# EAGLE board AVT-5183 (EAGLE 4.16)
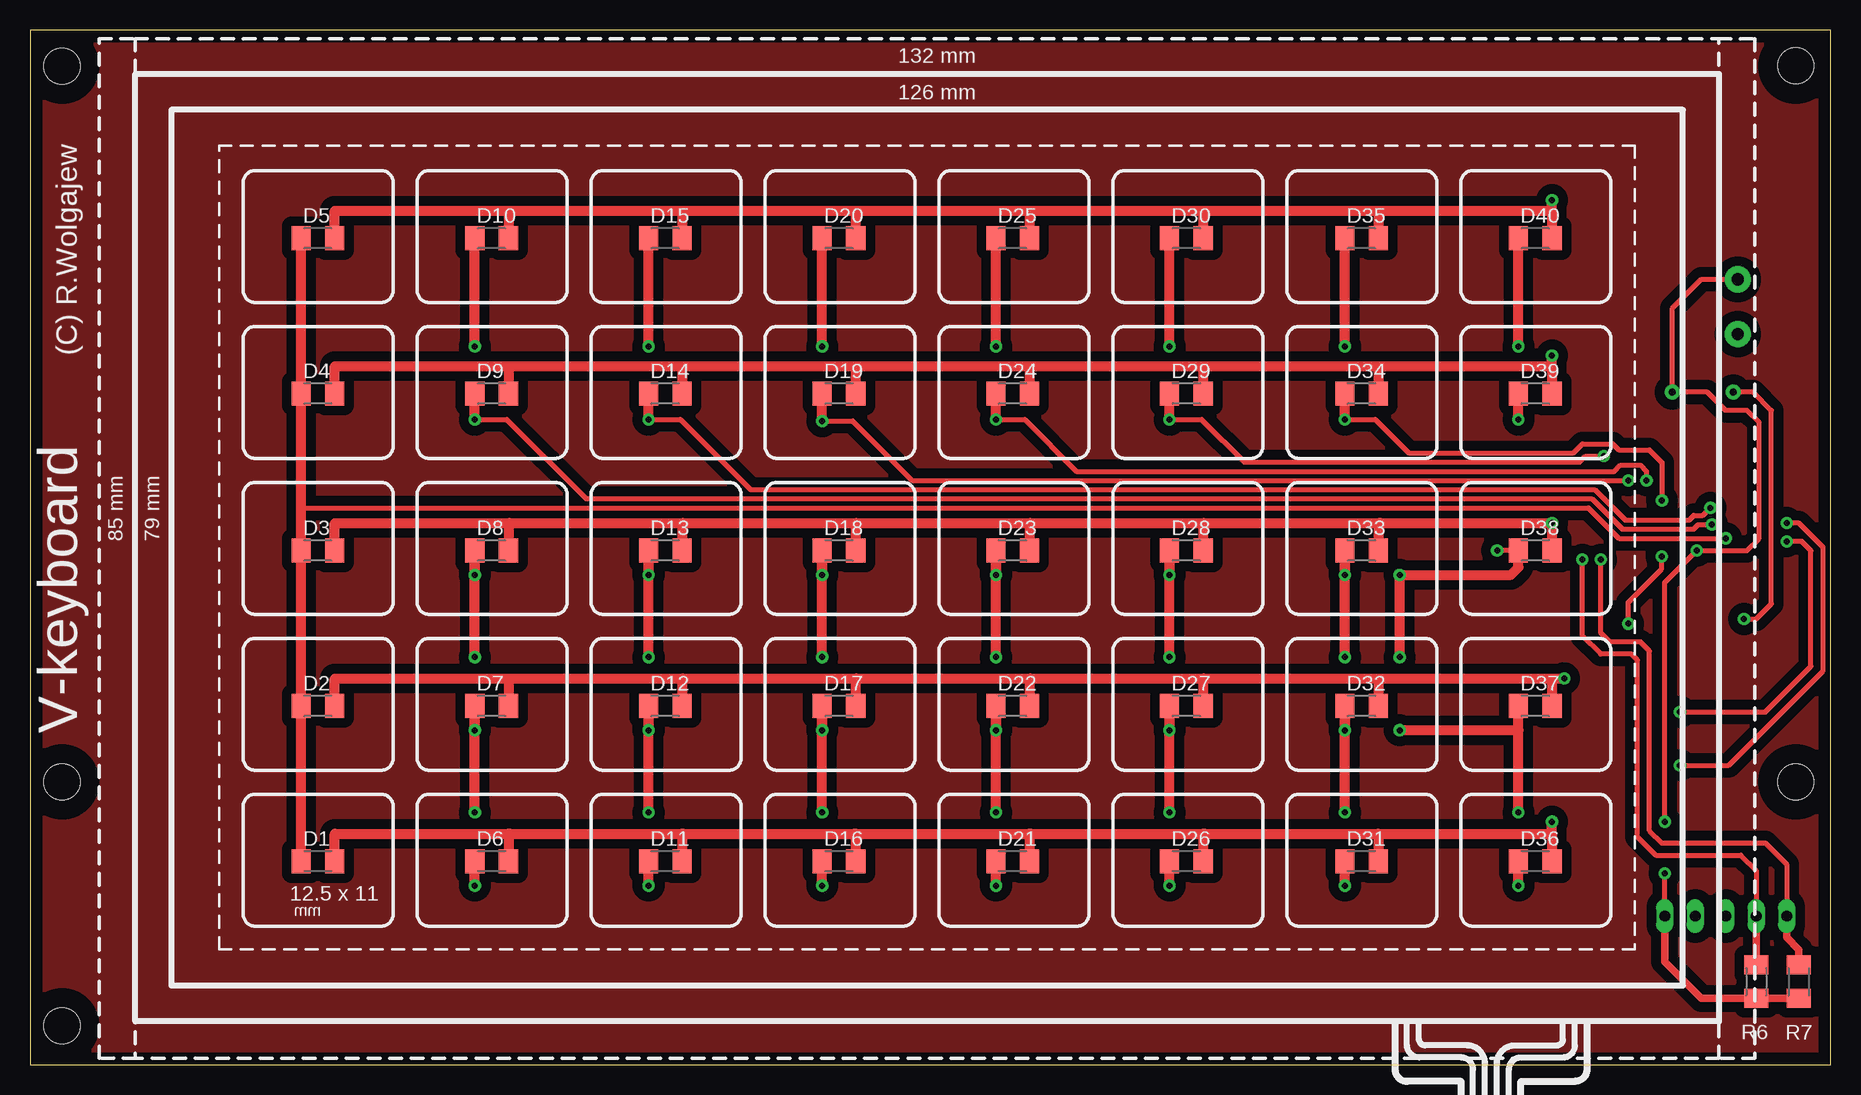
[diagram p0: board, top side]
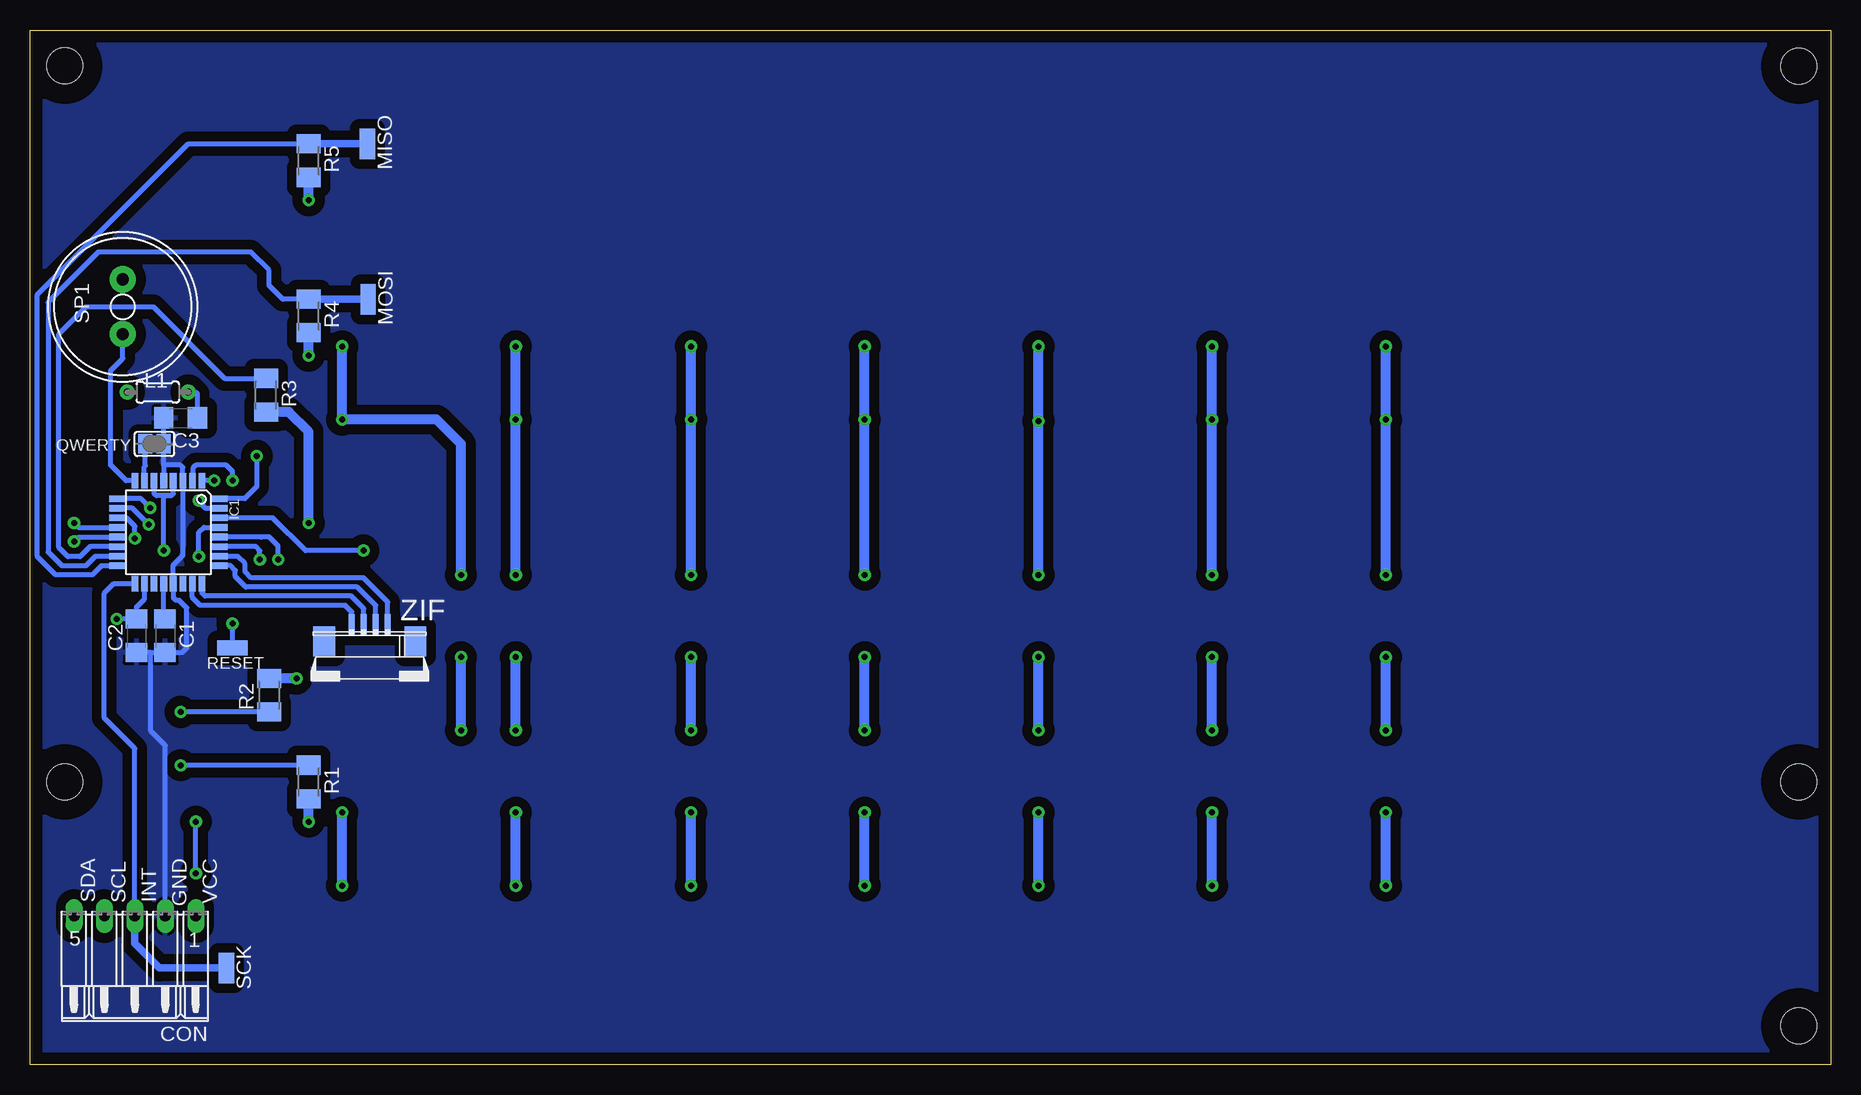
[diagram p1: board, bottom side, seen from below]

Size 150.09 x 86.28 mm. Coordinates in mm from the lower left corner, seen from the top.
Outline: 0,0 150.09,0 150.09,86.28 0,86.28 0,0
Copper layers (1*16): Top 0.035mm / dielectric 1.5mm / Bottom 0.035mm
Design rules "default": minimum track width 10mil, minimum drill 24mil, track to track 8mil, track to pad 8mil, pad to pad 8mil, via to via 8mil, smd to smd 8mil, copper to edge 40mil, drill to drill 8mil, minimum pad ring 10mil, minimum via ring 8mil, stop-mask expansion 4mil, vias tented up to drill 0mil, thermal gap 10mil
Holes 3 mm at 2.66,83.27 2.66,3.26 147.19,83.3 147.19,23.58 2.66,23.58
tRestrict: area 0.9,81.5 to 4.5,85.1; area 0.9,21.8 to 4.5,25.4; area 0.9,1.5 to 4.5,5.1; area 145.4,21.8 to 149,25.4; area 145.4,81.5 to 149,85.1
bRestrict: area 0.9,81.5 to 4.5,85.1; area 0.9,21.8 to 4.5,25.4; area 0.9,1.5 to 4.5,5.1; area 145.4,21.8 to 149,25.4; area 145.4,81.5 to 149,85.1

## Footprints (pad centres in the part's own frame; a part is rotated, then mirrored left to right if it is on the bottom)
C1206 = smd 1.6 x 1.8: 1 -1.4,0; 2 1.4,0
05PA = drill 0.914 long: 1 -5.08,0; 2 -2.54,0; 3 0,0; 4 2.54,0; 5 5.08,0
M1206 = smd 1.6 x 2: A 1.4,0; C -1.4,0
TQFP32-08 = smd 1.27 x 0.559: 1 -4.293,2.8; 2 -4.293,2; 3 -4.293,1.2; 4 -4.293,0.4; 5 -4.293,-0.4; 6 -4.293,-1.2; 7 -4.293,-2; 8 -4.293,-2.8; 17 4.293,-2.8; 18 4.293,-2; 19 4.293,-1.2; 20 4.293,-0.4; 21 4.293,0.4; 22 4.293,1.2; 23 4.293,2; 24 4.293,2.8 | smd 0.559 x 1.27: 9 -2.8,-4.293; 10 -2,-4.293; 11 -1.2,-4.293; 12 -0.4,-4.293; 13 0.4,-4.293; 14 1.2,-4.293; 15 2,-4.293; 16 2.8,-4.293; 25 2.8,4.293; 26 2,4.293; 27 1.2,4.293; 28 0.4,4.293; 29 -0.4,4.293; 30 -1.2,4.293; 31 -2,4.293; 32 -2.8,4.293
0204/5 = drill 0.6 pad 1.27 round: 1 -2.54,0; 2 2.54,0
SMD1,27-2,54 = smd 1.27 x 2.54: 1 0,0
PANEL = smd 0.5 x 1.8 bottom: 1 49.49,-5.94; 2 48.49,-5.94; 3 47.49,-5.94; 4 46.49,-5.94 | smd 1.8 x 2.5 bottom: P$5 44.19,-7.34; P$6 51.79,-7.34
SJ = smd 1.168 x 1.6: 1 -0.762,0; 2 0.762,0
M1206' = smd 1.6 x 2: 1 -1.4,0; 2 1.4,0
AL11P = drill 1.016 pad 2.184 round: + 2.286,0; - -2.286,0

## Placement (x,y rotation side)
C1  [C1206]  138.83,35.78 270 bottom
C2  [C1206]  141.22,35.78 270 bottom
C3  100nF  [C1206]  137.54,53.94 0 bottom
CON  [05PA]  141.35,12.41 180 bottom
D1  [M1206]  24,16.98 0 top
D2  [M1206]  24,29.93 0 top
D3  [M1206]  24,42.89 0 top
D4  [M1206]  24,55.97 0 top
D5  [M1206]  24,68.92 0 top
D6  [M1206]  38.48,16.98 0 top
D7  [M1206]  38.48,29.93 0 top
D8  [M1206]  38.48,42.89 0 top
D9  [M1206]  38.48,55.97 0 top
D10  [M1206]  38.48,68.92 0 top
D11  [M1206]  52.95,16.98 0 top
D12  [M1206]  52.95,29.93 0 top
D13  [M1206]  52.95,42.89 0 top
D14  [M1206]  52.95,55.97 0 top
D15  [M1206]  52.95,68.92 0 top
D16  [M1206]  67.43,16.98 0 top
D17  [M1206]  67.43,29.93 0 top
D18  [M1206]  67.43,42.89 0 top
D19  [M1206]  67.43,55.97 0 top
D20  [M1206]  67.43,68.92 0 top
D21  [M1206]  81.91,16.98 0 top
D22  [M1206]  81.91,29.93 0 top
D23  [M1206]  81.91,42.89 0 top
D24  [M1206]  81.91,55.97 0 top
D25  [M1206]  81.91,68.92 0 top
D26  [M1206]  96.39,16.98 0 top
D27  [M1206]  96.39,29.93 0 top
D28  [M1206]  96.39,42.89 0 top
D29  [M1206]  96.39,55.97 0 top
D30  [M1206]  96.39,68.92 0 top
D31  [M1206]  110.99,16.98 0 top
D32  [M1206]  110.99,29.93 0 top
D33  [M1206]  110.99,42.89 0 top
D34  [M1206]  110.99,55.97 0 top
D35  [M1206]  110.99,68.92 0 top
D36  [M1206]  125.47,16.98 0 top
D37  [M1206]  125.47,29.93 0 top
D38  [M1206]  125.47,42.89 0 top
D39  [M1206]  125.47,55.97 0 top
D40  [M1206]  125.47,68.92 0 top
IC1  MEGA8-TQFP32  [TQFP32-08]  138.55,44.41 270 bottom
L1  [0204/5]  139.44,56.1 180 bottom
MISO  [SMD1,27-2,54]  121.97,76.8 180 bottom
MOSI  [SMD1,27-2,54]  121.92,63.84 180 bottom
PANEL  PANEL  [PANEL]  73.78,42.63 0 top
QWERTY  [SJ]  139.72,51.78 0 bottom
R1  [M1206']  126.87,23.58 270 bottom
R2  [M1206']  130.17,30.82 90 bottom
R3  [M1206']  130.42,55.84 270 bottom
R4  [M1206']  126.87,62.45 270 bottom
R5  [M1206']  126.87,75.4 270 bottom
R6  [M1206']  143.89,6.95 90 top
R7  [M1206']  147.44,6.95 90 top
RESET  [SMD1,27-2,54]  133.22,34.76 270 bottom
SCK  [SMD1,27-2,54]  133.73,8.09 180 bottom
SP1  [AL11P]  142.36,63.21 90 bottom

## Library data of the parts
C1-C3 L1 R1-R7 = rcl
CON = con-amp-quick
D1-D40 = RW_smd_LED
IC1 = atmel
MISO MOSI RESET SCK = wirepad
PANEL = RW_panel_outline
QWERTY = jumper
SP1 = buzzer

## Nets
+5V: C3.2 CON.1 IC1.4 IC1.6 L1.1 R6.1 R7.1 SP1.+
GND: C1.2 C2.2 C3.1 CON.2 IC1.3 IC1.5 IC1.21 QWERTY.2
N$1: D1.C D2.C D3.C D4.C D5.C IC1.11
N$2: D6.C D7.C D8.C D9.C D10.C IC1.10
N$3: D11.C D12.C D13.C D14.C D15.C IC1.9
N$4: D16.C D17.C D18.C D19.C D20.C IC1.2
N$5: D21.C D22.C D23.C D24.C D25.C IC1.1
N$6: D26.C D27.C D28.C D29.C D30.C IC1.32
N$7: D31.C D32.C D33.C D34.C D35.C IC1.31
N$8: D36.C D37.C D38.C D39.C D40.C IC1.30
N$9: D1.A D6.A D11.A D16.A D21.A D26.A D31.A D36.A R1.2
N$10: D2.A D7.A D12.A D17.A D22.A D27.A D32.A D37.A R2.2
N$11: D3.A D8.A D13.A D18.A D23.A D28.A D33.A D38.A R3.2
N$12: D4.A D9.A D14.A D19.A D24.A D29.A D34.A D39.A R4.2
N$13: D5.A D10.A D15.A D20.A D25.A D30.A D35.A D40.A R5.2
N$14: IC1.23 PANEL.1
N$15: IC1.24 PANEL.2
N$16: IC1.25 PANEL.3
N$17: IC1.26 PANEL.4
N$18: IC1.7 QWERTY.1
N$19: C1.1 IC1.20
N$20: C2.1 IC1.18 L1.2
N$21: CON.3 IC1.17 SCK.1
N$22: IC1.15 MOSI.1 R4.1
N$23: IC1.16 MISO.1 R5.1
N$24: IC1.12 R1.1
N$25: IC1.13 R2.1
N$26: IC1.14 R3.1
N$27: IC1.8 SP1.-
N$28: CON.4 IC1.28 R6.2
N$29: CON.5 IC1.27 R7.2
N$30: IC1.29 RESET.1

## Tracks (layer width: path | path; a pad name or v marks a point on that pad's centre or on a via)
+5V  (via drill 0.5 pad 1.02)
  Top 0.406: SP1.+ 139.31,65.49 136.9,63.08 L1.1 139.82,56.1 141.35,54.57 143.12,54.57 144.14,53.56 144.14,43.9 143.12,42.89 v138.93,42.89 136.27,40.22 v136.27,20.28 | CON.1 v136.27,15.96
  Top 0.61: R7.1 R6.1 139.32,5.55 136.27,8.6 CON.1
  Bottom 0.406: IC1.6 139.75,47.64 139.57,47.46 138.32,47.46 | 138.32,47.46 138.15,47.64 IC1.4 | 138.32,47.46 138.93,47.46 v138.93,42.89 | v136.27,15.96 v136.27,20.28 | C3.2 136.14,55.97 136.27,56.1 L1.1
GND
  Bottom 0.406: IC1.5 138.96,50 | 138.96,50 QWERTY.2 138.93,51.78 138.94,51.78 C3.1 | 138.96,50 138.98,50 | 138.96,50 137.54,50 137.35,49.82 IC1.3 137.33,48.7 137.33,42.51 138.15,41.69 IC1.21 138.15,40.08 138.12,40.04 138.12,38.93 137.92,38.72 137.64,38.72 137.03,38.11 137.03,34.76 137.41,34.38 138.93,34.38 138.94,34.38 C1.2 | C1.2 138.94,34.88 138.93,34.89 | C2.2 140.99,34.38 140.02,34.38 | 140.02,34.38 C1.2 | CON.2 138.81,26.63 140.02,27.85 140.02,34.38
  pour Bottom (isolate 0.813): 0.63,85.81 149.73,85.81 149.73,0.47 0.63,0.47
N$1  (via drill 0.5 pad 1.02)
  Top 0.406: v141.35,43.9 132.46,43.9 129.92,46.44 22.6,46.44
  Top 0.813: 22.6,56.1 D4.C 22.6,46.44 D3.C | 22.6,56.1 D5.C | 22.6,56.1 22.73,56.1 | D3.C 22.47,42.89 | D2.C D3.C | D2.C 22.47,29.93 | D2.C D1.C 22.47,16.98
  Bottom 0.406: IC1.11 142.04,45.61 141.35,44.92 v141.35,43.9
N$2  (via drill 0.5 pad 1.02)
  Top 0.406: v140.2,45.05 139.06,45.05 138.68,44.67 132.71,44.67 130.17,47.21 46.35,47.21 39.75,53.81 v37.08,53.81
  Top 0.813: D10.C 37.08,59.78 v37.08,59.91 | D9.C v37.08,53.81 | v37.08,40.86 D8.C 37.08,33.87 v37.08,34 | v37.08,27.9 37.08,29.81 D7.C v37.08,21.04 | D6.C 37.08,17.11 v37.08,14.95
  Bottom 0.406: IC1.10 141.57,46.41 v140.2,45.05
  Bottom 0.813: v37.08,59.91 v37.08,53.81 v37.08,40.86 | v37.08,27.9 v37.08,34 | v37.08,14.95 v37.08,21.04
N$3  (via drill 0.5 pad 1.02)
  Top 0.406: v140.08,46.44 139.44,45.81 138.68,45.81 138.3,45.43 132.96,45.43 130.42,47.97 60.07,47.97 54.22,53.81 v51.56,53.81
  Top 0.813: D15.C 51.55,59.78 v51.56,59.91 | D14.C 51.55,55.84 51.56,55.84 v51.56,53.81 | v51.56,40.86 D13.C v51.56,34 | v51.56,27.9 D12.C v51.56,21.04 | D11.C v51.56,14.95
  Bottom 0.406: IC1.9 140.84,47.21 v140.08,46.44
  Bottom 0.813: v51.56,59.91 v51.56,53.81 v51.56,40.86 | v51.56,27.9 v51.56,34 | v51.56,14.95 v51.56,21.04
N$4  (via drill 0.5 pad 1.02)
  Top 0.406: v66.04,53.68 68.58,53.68 73.53,48.73 v133.22,48.73
  Top 0.813: D20.C v66.03,59.91 v66.04,59.91 | D19.C v66.04,53.68 | v66.04,40.86 D18.C v66.04,34 | v66.04,27.9 D17.C v66.04,21.04 | D16.C v66.04,14.95
  Bottom 0.406: v133.22,48.73 133.22,49.49 133.73,50 136.27,50 136.52,49.75 136.52,48.73 IC1.2
  Bottom 0.813: v66.04,59.91 v66.04,53.68 v66.04,40.86 | v66.04,27.9 v66.04,34 | v66.04,14.95 v66.04,21.04
N$5  (via drill 0.5 pad 1.02)
  Top 0.406: v80.51,53.81 82.93,53.81 87.24,49.49 132.07,49.49 132.58,50 134.23,50 134.74,49.49 v134.74,48.73
  Top 0.813: v80.51,59.91 D25.C | D24.C v80.51,53.81 | v80.51,40.86 D23.C v80.51,34 | v80.51,27.9 D22.C v80.51,21.04 | D21.C 80.51,16.85 v80.51,14.95
  Bottom 0.406: IC1.1 135.73,48.73 v134.74,48.73
  Bottom 0.813: v80.51,59.91 v80.51,53.81 v80.51,40.86 | v80.51,27.9 v80.51,34 | v80.51,14.95 v80.51,21.04
N$6  (via drill 0.5 pad 1.02)
  Top 0.406: v131.19,50.76 129.66,50.76 129.15,50.25 101.21,50.25 97.66,53.81 v94.99,53.81 94.97,53.81
  Top 0.813: v94.99,59.91 D30.C | D29.C v94.99,53.81 | v94.99,40.86 D28.C v94.99,34 | v94.99,27.9 94.99,29.81 D27.C v94.99,21.04 | D26.C v94.99,14.95
  Bottom 0.406: IC1.32 132.2,47.21 131.19,48.22 v131.19,50.76
  Bottom 0.813: v94.99,59.91 v94.99,53.81 v94.99,40.86 | v94.99,27.9 v94.99,34 | v94.99,14.95 v94.99,21.04
N$7  (via drill 0.5 pad 1.02)
  Top 0.406: v136.04,47.05 136.04,50.23 135,51.27 132.46,51.27 131.95,51.78 129.41,51.78 128.65,51.02 114.93,51.02 112.14,53.81 v109.6,53.81
  Top 0.813: v109.6,59.91 D35.C | D34.C v109.6,53.81 | v109.6,40.86 D33.C v109.6,34 | v109.6,27.9 D32.C v109.6,21.04 | D31.C v109.6,14.95
  Bottom 0.406: v136.04,47.05 136.04,46.98 135.47,46.41 IC1.31
  Bottom 0.813: v109.6,59.91 v109.6,53.81 v109.6,40.86 | v109.6,27.9 v109.6,34 | v109.6,14.95 v109.6,21.04
N$8  (via drill 0.5 pad 1.02)
  Top 0.406: D38.C v122.3,42.89
  Top 0.813: D40.C v124.07,59.91 | D39.C 124.07,56.09 124.07,56.1 v124.07,53.81 | D37.C 124.07,27.9 | 124.07,27.9 v124.07,21.05 v124.07,21.04 | D36.C 124.07,17.1 124.07,17.11 v124.07,14.95 | 124.07,27.9 | 124.07,27.9 v114.17,27.9 | v114.17,34 v114.17,40.86 123.44,40.86 124.07,41.49 D38.C
  Bottom 0.406: IC1.30 129.85,45.61 127.12,42.89 v122.3,42.89
  Bottom 0.813: v124.07,59.91 v124.07,53.81 116.2,53.81 114.17,51.78 114.17,50.76 v114.17,40.86 | v114.17,27.9 v114.17,34 | v124.07,14.95 v124.07,21.04
N$9  (via drill 0.5 pad 1.02)
  Top 0.813: D1.A 25.4,19.27 40,19.27 | 40,19.27 54.48,19.27 | 54.48,19.27 68.7,19.27 | 68.7,19.27 83.43,19.27 | 83.43,19.27 97.91,19.27 | 97.91,19.27 112.39,19.27 | 112.39,19.27 126.87,19.27 | D36.A 126.87,19.27 | D31.A 112.39,19.27 | D26.A 97.79,19.27 97.91,19.27 | D21.A 83.31,19.27 83.43,19.27 | D16.A 68.83,19.27 68.7,19.27 | D11.A 54.35,19.27 54.48,19.27 | D6.A 39.88,19.27 40,19.27 | 126.87,19.27 v126.87,20.28
  Bottom 0.813: R1.2 v126.87,20.28
N$10  (via drill 0.5 pad 1.02)
  Top 0.813: D2.A 25.4,32.22 39.75,32.22 | 39.75,32.22 54.48,32.22 | 54.48,32.22 68.96,32.22 | 68.96,32.22 83.43,32.22 | 83.43,32.22 97.91,32.22 | 97.91,32.22 112.39,32.22 | D37.A 126.87,32.22 | D32.A 112.39,32.22 | D27.A 97.79,32.22 97.91,32.22 | D22.A 83.31,32.22 83.43,32.22 | D17.A 68.83,32.22 68.96,32.22 | D12.A 54.35,32.22 54.48,32.22 | D7.A 39.88,32.22 39.75,32.22 | 112.39,32.22 126.87,32.22 | 126.87,32.22 v127.88,32.22
  Bottom 0.813: R2.2 v127.88,32.22
N$11  (via drill 0.5 pad 1.02)
  Top 0.813: D3.A 25.4,45.17 40,45.17 | 40,45.17 54.48,45.17 | 54.48,45.17 68.96,45.17 | 68.96,45.17 83.43,45.17 | 83.43,45.17 97.91,45.17 | 97.91,45.17 112.64,45.17 | D38.A v126.87,45.17 112.64,45.17 | D33.A 112.39,45.17 112.64,45.17 | D28.A 97.79,45.17 97.91,45.17 | D23.A 83.31,45.17 83.43,45.17 | D18.A 68.83,45.17 68.96,45.17 | D13.A 54.35,45.17 54.48,45.17 | D8.A 39.88,45.17 40,45.17
  Bottom 0.813: v126.87,45.17 126.87,52.79 128.52,54.45 R3.2
N$12  (via drill 0.5 pad 1.02)
  Top 0.813: D4.A 25.4,58.26 40,58.26 | 40,58.26 54.48,58.26 | 54.48,58.26 68.96,58.26 | 68.96,58.26 83.18,58.26 | 83.18,58.26 97.91,58.26 | 97.91,58.26 112.39,58.26 | 112.39,58.26 126.87,58.26 | D39.A 126.87,56.1 126.87,58.26 | 112.39,58.26 112.39,58.13 D34.A | 97.91,58.26 97.91,58.13 97.79,58.13 D29.A | 83.18,58.26 83.18,58.13 83.31,58.13 D24.A | 68.96,58.26 68.96,58.13 68.83,58.13 D19.A | 54.48,58.26 54.48,58.13 54.35,58.13 D14.A | 40,58.26 40,58.13 39.88,58.13 D9.A | 126.87,58.26 v126.87,59.14
  Bottom 0.813: R4.2 v126.87,59.14
N$13  (via drill 0.5 pad 1.02)
  Top 0.813: D5.A 25.4,71.21 40,71.21 | 40,71.21 54.48,71.21 | 54.48,71.21 68.96,71.21 | 68.96,71.21 83.43,71.21 | 83.43,71.21 97.91,71.21 | 97.91,71.21 112.64,71.21 | 126.87,69.05 | 126.87,69.05 D40.A | 112.64,71.21 112.64,71.08 112.39,71.08 D35.A | 97.91,71.21 97.91,71.08 97.79,71.08 D30.A | 83.43,71.21 83.43,71.08 83.31,71.08 D25.A | 68.96,71.21 68.96,71.08 68.83,71.08 D20.A | 54.48,71.21 54.48,71.08 54.35,71.08 D15.A | 40,71.21 40,71.08 39.88,71.08 D10.A | 112.64,71.21 126.87,71.21 | 126.87,71.21 126.87,69.05 | 126.87,71.21 v126.87,72.09 v126.87,72.1
  Bottom 0.813: v126.87,72.1 R5.2
N$14
  Bottom 0.406: PANEL.1 123.27,37.77 123.82,38.32 135.91,38.32 136.57,38.98 136.57,40.12 IC1.23
N$15
  Bottom 0.406: PANEL.2 122.27,38.04 123.31,39.08 135.5,39.08 135.76,39.33 135.76,40.09 135.75,40.1 IC1.24
N$16
  Bottom 0.406: PANEL.3 121.27,38.31 122.8,39.84 132.1,39.84 132.99,40.7 132.99,41.24 133.37,41.62 134.21,41.62 134.23,41.59 IC1.25
N$17
  Bottom 0.406: PANEL.4 120.27,38.58 122.3,40.6 131.64,40.6 132.18,41.13 132.18,41.8 132.79,42.41 134.23,42.41 134.24,42.41 IC1.26 134.3,42.41 134.31,42.41
N$18
  Bottom 0.406: QWERTY.1 140.48,49.95 140.56,49.87 140.56,48.73 140.55,48.72 IC1.7
N$19
  Bottom 0.406: C1.1 138.96,37.68 138.95,37.69 IC1.20
N$20  (via drill 0.5 pad 1.02)
  Top 0.406: v142.87,37.17 143.89,37.17 145.16,38.44 145.16,54.57 143.63,56.1 L1.2
  Bottom 0.406: IC1.18 140.55,38.86 141.22,38.19 C2.1 | C2.1 141.09,37.05 | C2.1 142.61,37.18 v142.87,37.17
N$21
  Bottom 0.406: IC1.17 143.1,40.12 143.89,39.33 143.89,28.92 141.35,26.38 CON.3
  Bottom 0.61: SCK.1 139.31,8.09 141.35,10.12 CON.3
N$22
  Bottom 0.406: 126.89,63.84 126.89,63.85 R4.1 129.03,63.84 130.17,64.99 130.17,66.26 131.69,67.78 144.39,67.78 148.58,63.59 148.58,42.76 147.44,41.62 145.41,41.62 144.62,42.41 IC1.15
  Bottom 0.61: MOSI.1 R4.1 126.89,63.84
N$23
  Bottom 0.406: 126.84,76.8 126.85,76.8 R5.1 136.9,76.8 149.47,64.22 149.47,42.38 147.95,40.86 144.9,40.86 144.15,41.61 IC1.16
  Bottom 0.61: 126.84,76.8 MISO.1
N$24  (via drill 0.5 pad 1.02)
  Top 0.406: v137.54,24.98 141.6,24.98 149.47,32.85 149.47,43.14 147.44,45.17 v146.43,45.17
  Bottom 0.406: R1.1 129.15,24.98 v137.54,24.98 | IC1.12 146.06,44.81 v146.43,45.17
N$25  (via drill 0.5 pad 1.02)
  Top 0.406: v137.54,29.43 144.65,29.43 148.46,33.24 148.46,42.89 147.7,43.65 v146.43,43.65
  Bottom 0.406: IC1.13 146.06,44.01 v146.43,43.65 | R2.1 v137.54,29.43
N$26
  Bottom 0.406: IC1.14 145.09,43.21 145.92,42.38 146.93,42.38 147.7,43.14 147.7,60.92 145.41,63.21 139.82,63.21 133.85,57.24 R3.1
N$27
  Bottom 0.406: IC1.8 142.08,48.7 143.38,50 143.38,57.87 142.36,58.89 SP1.-
N$28  (via drill 0.5 pad 1.02)
  Top 0.406: v129.41,42.13 129.41,35.78 130.93,34.25 133.47,34.25 133.98,33.74 133.98,19.01 135.5,17.49 142.62,17.49 143.89,16.22 CON.4
  Top 0.61: CON.4 R6.2
  Bottom 0.406: 130.8,44.01 130.79,44.01 | v129.41,42.13 129.41,43.27 130.17,44.03 130.8,44.03 130.8,44.01 | IC1.28 134.23,44.03 134.22,44.01 130.8,44.01
N$29  (via drill 0.5 pad 1.02)
  Top 0.406: v130.93,42.13 130.93,36.03 131.69,35.27 134.23,35.27 135,34.51 135,19.52 136.01,18.5 144.65,18.5 146.43,16.73 CON.5
  Top 0.61: CON.5 146.43,10.63 147.44,9.61 R7.2
  Bottom 0.406: IC1.27 131.26,43.21 130.93,42.89 v130.93,42.13
N$30  (via drill 0.5 pad 1.02)
  Top 0.406: v136.01,42.38 136.01,41.36 133.22,38.57 v133.22,36.79
  Bottom 0.406: IC1.29 135.61,44.81 136.01,44.41 v136.01,42.38 | RESET.1 v133.22,36.79
N$31
  pour Top (isolate 0.813): 0.38,86.07 149.73,86.07 149.73,0.47 0.38,0.47

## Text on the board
tNames: 132 mm | 126 mm | (C) R.Wolgajew | 85 mm | 79 mm | V-keyboard | 12.5 x 11 | mm
bNames: ZIF | VCC | GND | SDA | INT | SCL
